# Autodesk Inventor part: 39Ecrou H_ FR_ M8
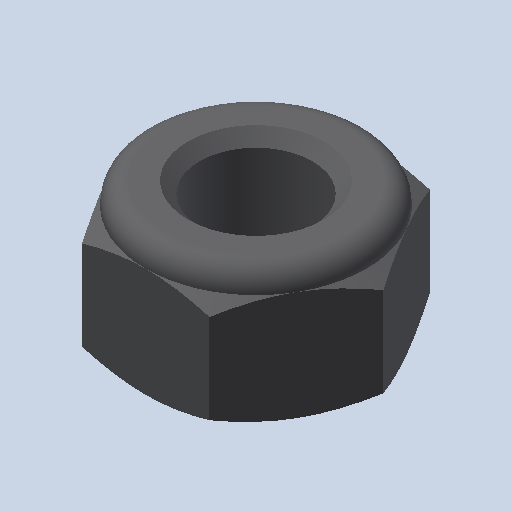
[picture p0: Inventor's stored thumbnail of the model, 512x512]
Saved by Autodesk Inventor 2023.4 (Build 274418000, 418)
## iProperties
Created: 2011-01
Part Number: 39Ecrou H_ FR_ M8
Document SubType Name: Modeling
Designer: eric
Density: 1 g/cm^3
Mass: 0.816097 g
Surface Area: 6.75325 cm^2
Volume: 0.816097 cm^3
Material: Générique
Appearance: Red
Author: eric
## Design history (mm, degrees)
feature "Base1"
node "Corps solides"
node "Corps surfaciques"
node "Solide1"
